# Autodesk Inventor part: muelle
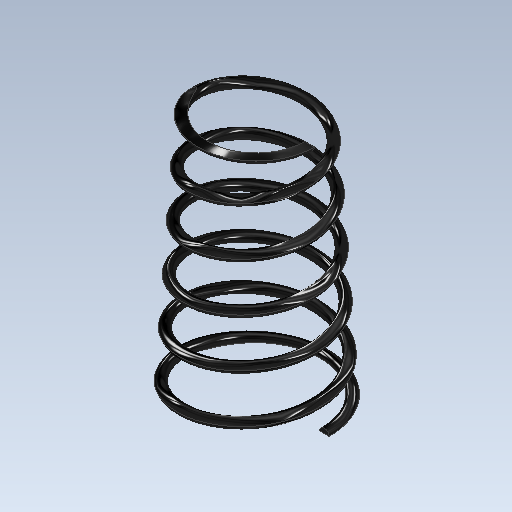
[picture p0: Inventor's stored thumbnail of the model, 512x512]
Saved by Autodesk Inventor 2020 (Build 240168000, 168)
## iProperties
Created: 2022-02
Part Number: muelle
Material: Genérico
Document SubType Name: Modeling
Designer: Eresthor
Density: 1 g/cm^3
Appearance: Negro
Author: Eresthor
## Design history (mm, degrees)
sketch "Boceto1"
  geometry: L1 (0, 0)-(0, 1.609); C1 r 0.5 at (7, 0.5)
  constraints: 2 end point, 1 centre point, 1 vertical
feature "Bobina1" sketch "Boceto1" pitch "d3" = 10; turns "d5" = 5; dims "d4" = 25, "d6" = -3.5 deg, angle "d7" = 90 deg, angle "d8" = 90 deg, "d9" = 90 deg, "d10" = 90 deg
sketch "Boceto2"
  geometry: L1 (0, 0)-(-0.5, 0); L2 (-0.5, 0)-(-0.5, 0.5); L3 (-0.5, 0.5)-(11.5, 0.5); L4 (11.5, 0.5)-(11.5, 0); L5 (11.5, 0)-(0, 0); 1 further point
  constraints: 10 end point, 2 perpendicular, 1 horizontal, 1 point on line
  dimensions: "d11" = 0.5 distance of L1.start L1.end; "d12" = 0.5 distance of L1.end L2.end; "d13" = 12 distance of L2.end L3.end; "d14" = 0.5 distance of L3.end L4.end
extrude "Extrusión1" cut sketch "Boceto2" distance "d15" = 6; taper "d16" = 0 deg
sketch "Boceto3"
  geometry: L1 (-14.457, 0)-(-14.457, -0.5); L2 (0.5, 0)-(-14.457, 0); L3 (-14.457, 0)-(-14.457, -0.5); L4 (-14.457, -0.5)-(0.5, -0.5); L5 (0.5, -0.5)-(0.5, 0); 2 further points
  constraints: 10 end point, 2 parallel, 1 horizontal, 1 perpendicular
extrude "Extrusión2" cut sketch "Boceto3" distance "d17" = 8; taper "d18" = 0 deg
node "Sólido1"
